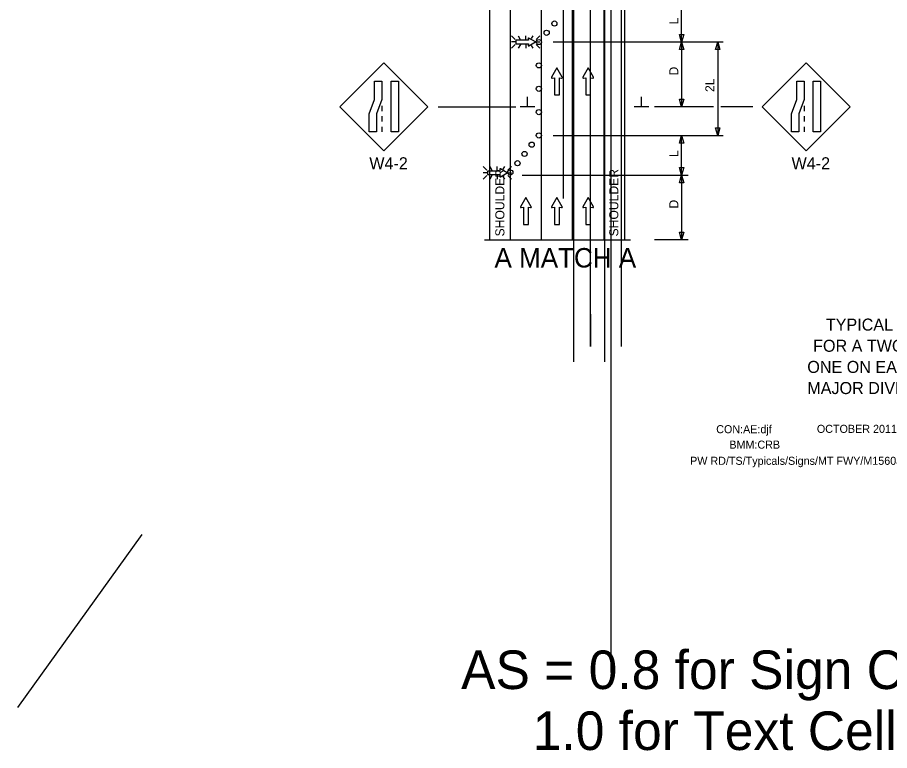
# Model space of a CAD drawing. Extents: x 16552 to 19508, y 5713 to 7079.
# Drawn here: x 16552 to 17224, y 5713 to 6279 of the extents above; entities that cross this region are included whole.
import ezdxf

# ---------------------------------------------------------------- set-up
doc = ezdxf.new("R2010")
doc.units = 0
for name, color, linetype in [('ALI_LEGAL_EX', 7, 'Continuous'), ('BORDER', 7, 'Continuous'), ('BORDER_SIGNAL_WO', 7, 'Continuous'), ('MT_SCRATCH_LEVEL_E', 7, 'Continuous'), ('PAVT_EDGE_EX', 7, 'Continuous'), ('TRAFFIC_SIGNS_PR', 7, 'Continuous'), ('TYPICAL_TEXT_DIMEN_PR', 7, 'Continuous')]:
    doc.layers.add(name, color=color, linetype=linetype)

msp = doc.modelspace()

# ---------------------------------------------------------------- linework, layer by layer
at = {"layer": 'ALI_LEGAL_EX'}
for p, q in [((16980.68, 6974.12), (16980.68, 6155.98)), ((17004.68, 6974.12), (17004.68, 6155.98)), ((16980.68, 6877.04), (16980.68, 6013.12)), ((17004.68, 6877.04), (17004.68, 6013.12)), ((16973.01, 6139.03), (16973.01, 6639.38)), ((16993.65, 6024.8), (16993.65, 6525.15)), ((17017.65, 6024.8), (17017.65, 6525.15)), ((16955.93, 6107.09), (16955.93, 6383.76)), ((16979.93, 6107.09), (16979.93, 6383.76)), ((17009.75, 5773.57), (17009.75, 6383.76))]:
    msp.add_line(p, q, dxfattribs=at)
for points in [[(16955.93, 6207.09), (16955.93, 6232.09)], [(16979.93, 6207.09), (16979.93, 6232.09)], [(16955.93, 6107.09), (16955.93, 6132.09)], [(16979.93, 6107.09), (16979.93, 6132.09)], [(16993.65, 6049.8), (16993.65, 6024.8)]]:
    msp.add_lwpolyline(points, dxfattribs=at)
at = {"layer": 'MT_SCRATCH_LEVEL_E'}
for p, q in [((16967.85, 6239.76), (16963.74, 6232.52)), ((16972, 6232.52), (16967.85, 6239.76)), ((16991.9, 6239.76), (16987.79, 6232.52)), ((16996.05, 6232.52), (16991.9, 6239.76)), ((16964.22, 6231.84), (16966, 6232.15)), ((16966, 6232.15), (16966, 6218.89)), ((16969.74, 6218.89), (16969.74, 6232.15)), ((16969.74, 6232.15), (16971.52, 6231.84)), ((16988.27, 6231.84), (16990.05, 6232.15)), ((16990.05, 6232.15), (16990.05, 6218.89)), ((16993.79, 6218.89), (16993.79, 6232.15)), ((16993.79, 6232.15), (16995.57, 6231.84)), ((16966, 6218.89), (16969.74, 6218.89)), ((16990.05, 6218.89), (16993.79, 6218.89)), ((16943.95, 6139.9), (16939.84, 6132.66)), ((16948.09, 6132.66), (16943.95, 6139.9)), ((16967.85, 6139.9), (16963.74, 6132.66)), ((16972, 6132.66), (16967.85, 6139.9)), ((16991.9, 6139.9), (16987.79, 6132.66)), ((16996.05, 6132.66), (16991.9, 6139.9)), ((16940.32, 6131.97), (16942.1, 6132.29)), ((16942.1, 6132.29), (16942.1, 6119.03)), ((16945.84, 6119.03), (16945.84, 6132.29)), ((16945.84, 6132.29), (16947.61, 6131.97)), ((16964.22, 6131.97), (16966, 6132.29)), ((16966, 6132.29), (16966, 6119.03)), ((16969.74, 6119.03), (16969.74, 6132.29)), ((16969.74, 6132.29), (16971.52, 6131.97)), ((16988.27, 6131.97), (16990.05, 6132.29)), ((16990.05, 6132.29), (16990.05, 6119.03)), ((16993.79, 6119.03), (16993.79, 6132.29)), ((16993.79, 6132.29), (16995.57, 6131.97)), ((16942.1, 6119.03), (16945.84, 6119.03)), ((16966, 6119.03), (16969.74, 6119.03)), ((16990.05, 6119.03), (16993.79, 6119.03))]:
    msp.add_line(p, q, dxfattribs=at)
for centre, start, end in [((16964.15, 6232.29), 150.42484, 279.96381), ((16971.59, 6232.29), 260.03619, 29.77312), ((16988.2, 6232.29), 150.42484, 279.96381), ((16995.64, 6232.29), 260.03619, 29.77312), ((16940.24, 6132.43), 150.42484, 279.96381), ((16947.68, 6132.43), 260.03619, 29.77312), ((16964.15, 6132.43), 150.42484, 279.96381), ((16971.59, 6132.43), 260.03619, 29.77312), ((16988.2, 6132.43), 150.42484, 279.96381), ((16995.64, 6132.43), 260.03619, 29.77312)]:
    msp.add_arc(centre, 0.463, start, end, dxfattribs=at)
at = {"layer": 'PAVT_EDGE_EX'}
for p, q in [((16915.93, 6383.76), (16915.93, 6107.09)), ((16931.93, 6383.76), (16931.93, 6107.09)), ((17003.93, 6383.76), (17003.93, 6107.09)), ((17019.93, 6383.76), (17019.93, 6107.09))]:
    msp.add_line(p, q, dxfattribs=at)
at = {"layer": 'TRAFFIC_SIGNS_PR'}
for p, q in [((16935.71, 6261.75), (16932.89, 6264.57)), ((16938, 6264.57), (16939.63, 6261.75)), ((16943.79, 6261.75), (16943.79, 6264.57)), ((16949.26, 6264.57), (16948.05, 6262.48)), ((16954.69, 6264.57), (16951.88, 6261.75)), ((16935.71, 6259.72), (16932.89, 6259.72)), ((16935.71, 6257.69), (16932.89, 6254.87)), ((16939.66, 6257.69), (16938.03, 6254.87)), ((16943.79, 6257.69), (16943.79, 6254.87)), ((16947.97, 6257.05), (16949.24, 6254.87)), ((16951.88, 6259.72), (16954.69, 6259.72)), ((16954.69, 6254.87), (16951.88, 6257.69)), ((16834.51, 6243.73), (16800.57, 6209.79)), ((16868.45, 6209.79), (16834.51, 6243.73)), ((17160.07, 6243.73), (17126.13, 6209.79)), ((17194.02, 6209.79), (17160.07, 6243.73)), ((16800.57, 6209.79), (16834.51, 6175.85)), ((16832.95, 6210.4), (16832.95, 6206.4)), ((16834.51, 6175.85), (16868.45, 6209.79)), ((17126.13, 6209.79), (17160.07, 6175.85)), ((17158.52, 6210.4), (17158.52, 6206.4)), ((17160.07, 6175.85), (17194.02, 6209.79)), ((16832.95, 6202.4), (16832.95, 6198.4)), ((17158.52, 6202.4), (17158.52, 6198.4)), ((16832.95, 6194.4), (16832.95, 6190.4)), ((17158.52, 6194.4), (17158.52, 6190.4)), ((16913.83, 6160.8), (16911.01, 6163.62)), ((16916.13, 6163.62), (16917.76, 6160.8)), ((16921.92, 6160.8), (16921.92, 6163.62)), ((16927.39, 6163.62), (16926.18, 6161.53)), ((16932.82, 6163.62), (16930, 6160.8)), ((16913.83, 6158.77), (16911.01, 6158.77)), ((16913.83, 6156.74), (16911.01, 6153.92)), ((16917.78, 6156.74), (16916.15, 6153.92)), ((16921.92, 6156.74), (16921.92, 6153.92)), ((16926.1, 6156.1), (16927.36, 6153.92)), ((16930, 6158.77), (16932.82, 6158.77)), ((16932.82, 6153.92), (16930, 6156.74))]:
    msp.add_line(p, q, dxfattribs=at)
for points in [[(16945.62, 6262.4), (16945.85, 6261.11), (16936.12, 6261.11), (16936.12, 6258.36), (16945.85, 6258.36), (16945.62, 6257.06)], [(16946.12, 6256.71), (16951.43, 6259.72), (16946.12, 6262.76)], [(16923.74, 6161.45), (16923.97, 6160.15), (16914.25, 6160.15), (16914.25, 6157.41), (16923.97, 6157.41), (16923.74, 6156.11)], [(16924.24, 6155.75), (16929.55, 6158.77), (16924.24, 6161.81)]]:
    msp.add_lwpolyline(points, dxfattribs=at)
for points in [[(16832.95, 6229.46), (16832.95, 6215.48), (16828.77, 6204.38), (16828.77, 6190.4), (16823.15, 6190.4), (16823.15, 6204.38), (16827.33, 6215.48), (16827.33, 6229.46)], [(16845.62, 6229.46), (16845.62, 6190.4), (16840, 6190.4), (16840, 6229.46)], [(17158.52, 6229.46), (17158.52, 6215.48), (17154.34, 6204.38), (17154.34, 6190.4), (17148.72, 6190.4), (17148.72, 6204.38), (17152.9, 6215.48), (17152.9, 6229.46)], [(17171.19, 6229.46), (17171.19, 6190.4), (17165.57, 6190.4), (17165.57, 6229.46)]]:
    msp.add_lwpolyline(points, close=True, dxfattribs=at)
for centre in [(16965.93, 6273.93), (16959.93, 6266.79), (16953.93, 6259.65), (16953.93, 6241.65), (16953.93, 6223.65), (16953.93, 6205.65), (16953.93, 6187.65), (16948.43, 6180.52), (16942.94, 6173.39), (16937.44, 6166.26), (16931.94, 6159.14)]:
    msp.add_circle(centre, 2, dxfattribs=at)
for centre, start, end in [((16945.95, 6262.46), 61.48329, 189.95933), ((16945.95, 6257.01), 170.73078, 298.89165), ((16924.08, 6161.51), 61.48329, 189.95933), ((16924.08, 6156.05), 170.73078, 298.89165)]:
    msp.add_arc(centre, 0.341, start, end, dxfattribs=at)
at = {"layer": 'TYPICAL_TEXT_DIMEN_PR'}
for p, q in [((17064.03, 6259.65), (17064.03, 6288.21)), ((17064.03, 6259.65), (17062.46, 6265.51)), ((17062.46, 6265.51), (17064.03, 6265.51)), ((17064.03, 6265.51), (17065.6, 6265.51)), ((17065.6, 6265.51), (17064.03, 6259.65)), ((17096.07, 6259.65), (16964.93, 6259.65)), ((17062.46, 6253.79), (17064.03, 6259.65)), ((17064.03, 6253.79), (17062.46, 6253.79)), ((17064.03, 6259.65), (17064.03, 6209.65)), ((17064.03, 6259.65), (17065.6, 6253.79)), ((17065.6, 6253.79), (17064.03, 6253.79)), ((17090.26, 6253.79), (17091.83, 6259.65)), ((17091.83, 6253.79), (17090.26, 6253.79)), ((17091.83, 6259.65), (17093.4, 6253.79)), ((17091.83, 6259.65), (17091.83, 6187.65)), ((17093.4, 6253.79), (17091.83, 6253.79)), ((16945.22, 6209.65), (16945.22, 6217.44)), ((17033.15, 6209.65), (17033.15, 6217.44)), ((17064.03, 6209.65), (17062.46, 6215.51)), ((17062.46, 6215.51), (17064.03, 6215.51)), ((17064.03, 6215.51), (17065.6, 6215.51)), ((17065.6, 6215.51), (17064.03, 6209.65)), ((16876.41, 6209.65), (16936.23, 6209.65)), ((16950.84, 6209.65), (16939.59, 6209.65)), ((17038.78, 6209.65), (17027.53, 6209.65)), ((17088.65, 6209.65), (17043.03, 6209.65)), ((17118.85, 6209.65), (17094.37, 6209.65)), ((17091.83, 6187.65), (17090.26, 6193.51)), ((17090.26, 6193.51), (17091.83, 6193.51)), ((17091.83, 6193.51), (17093.4, 6193.51)), ((17093.4, 6193.51), (17091.83, 6187.65)), ((16964.93, 6187.65), (17096.07, 6187.65)), ((17062.46, 6181.79), (17064.03, 6187.65)), ((17064.03, 6157.09), (17064.03, 6187.65)), ((17064.03, 6187.65), (17065.6, 6181.79)), ((17064.03, 6181.79), (17062.46, 6181.79)), ((17065.6, 6181.79), (17064.03, 6181.79)), ((17064.03, 6157.09), (17062.46, 6162.95)), ((17062.46, 6162.95), (17064.03, 6162.95)), ((17064.03, 6162.95), (17065.6, 6162.95)), ((17065.6, 6162.95), (17064.03, 6157.09)), ((16941.19, 6157.09), (17069.03, 6157.09)), ((17062.46, 6151.22), (17064.03, 6157.09)), ((17064.03, 6157.09), (17064.03, 6107.09)), ((17064.03, 6157.09), (17065.6, 6151.22)), ((17064.03, 6151.22), (17062.46, 6151.22)), ((17065.6, 6151.22), (17064.03, 6151.22)), ((17064.03, 6107.09), (17062.46, 6112.95)), ((17062.46, 6112.95), (17064.03, 6112.95)), ((17064.03, 6112.95), (17065.6, 6112.95)), ((17065.6, 6112.95), (17064.03, 6107.09)), ((16912, 6107.09), (17024.65, 6107.09)), ((17069.03, 6107.09), (17043.03, 6107.09)), ((16647.75, 5880), (16551.91, 5746.64))]:
    msp.add_line(p, q, dxfattribs=at)

# ---------------------------------------------------------------- texts
at = {"layer": 'BORDER'}
for s, p in [('TYPICAL TEMPORARY TRAFFIC CONTROL', (17175.21, 6037.14)), ('FOR A TWO-LANE CLOSURE ON A FREEWAY,', (17165.41, 6020.84)), ('ONE ON EACH SIDE OF A GORE AREA AT A ', (17160.92, 6004.54)), ('MAJOR DIVERGENCE USING A TRIPLE STEP ', (17160.92, 5988.24))]:
    msp.add_text(s, height=9.3, dxfattribs=at).set_placement(p)
at = {"layer": 'BORDER_SIGNAL_WO'}
for s, height, p in [('CON:AE:djf  ', 6.2, (17090.69, 5958.06)), ('    OCTOBER 2011    ', 6.2, (17159.08, 5958.34)), ('BMM:CRB   ', 6.2, (17100.81, 5946.17)), ('PW RD/TS/Typicals/Signs/MT FWY/M1560a.dgn      ', 6.2, (17070.55, 5933.71)), ('AS = 0.8 for Sign Cells', 29.7271, (16894.01, 5760.83)), ('     1.0 for Text Cells', 29.7271, (16894.01, 5713.82))]:
    msp.add_text(s, height=height, dxfattribs=at).set_placement(p)
at = {"layer": 'TRAFFIC_SIGNS_PR'}
for p in [(16823.2, 6161.55), (17148.77, 6161.55)]:
    msp.add_text('W4-2', height=9.3, dxfattribs=at).set_placement(p)
at = {"layer": 'TYPICAL_TEXT_DIMEN_PR'}
for s, p in [('L', (17061.56, 6273.29)), ('D', (17061.47, 6233.87)), ('2L', (17089.28, 6221.15)), ('L', (17061.47, 6170.94)), ('SHOULDER', (16927.37, 6109.79)), ('SHOULDER', (17015.23, 6109.79)), ('D', (17061.47, 6131.3))]:
    msp.add_text(s, height=7, rotation=90, dxfattribs=at).set_placement(p)
msp.add_text('A MATCH A', height=15, dxfattribs=at).set_placement((16919.74, 6085.81))

doc.saveas('drawing.dxf')
